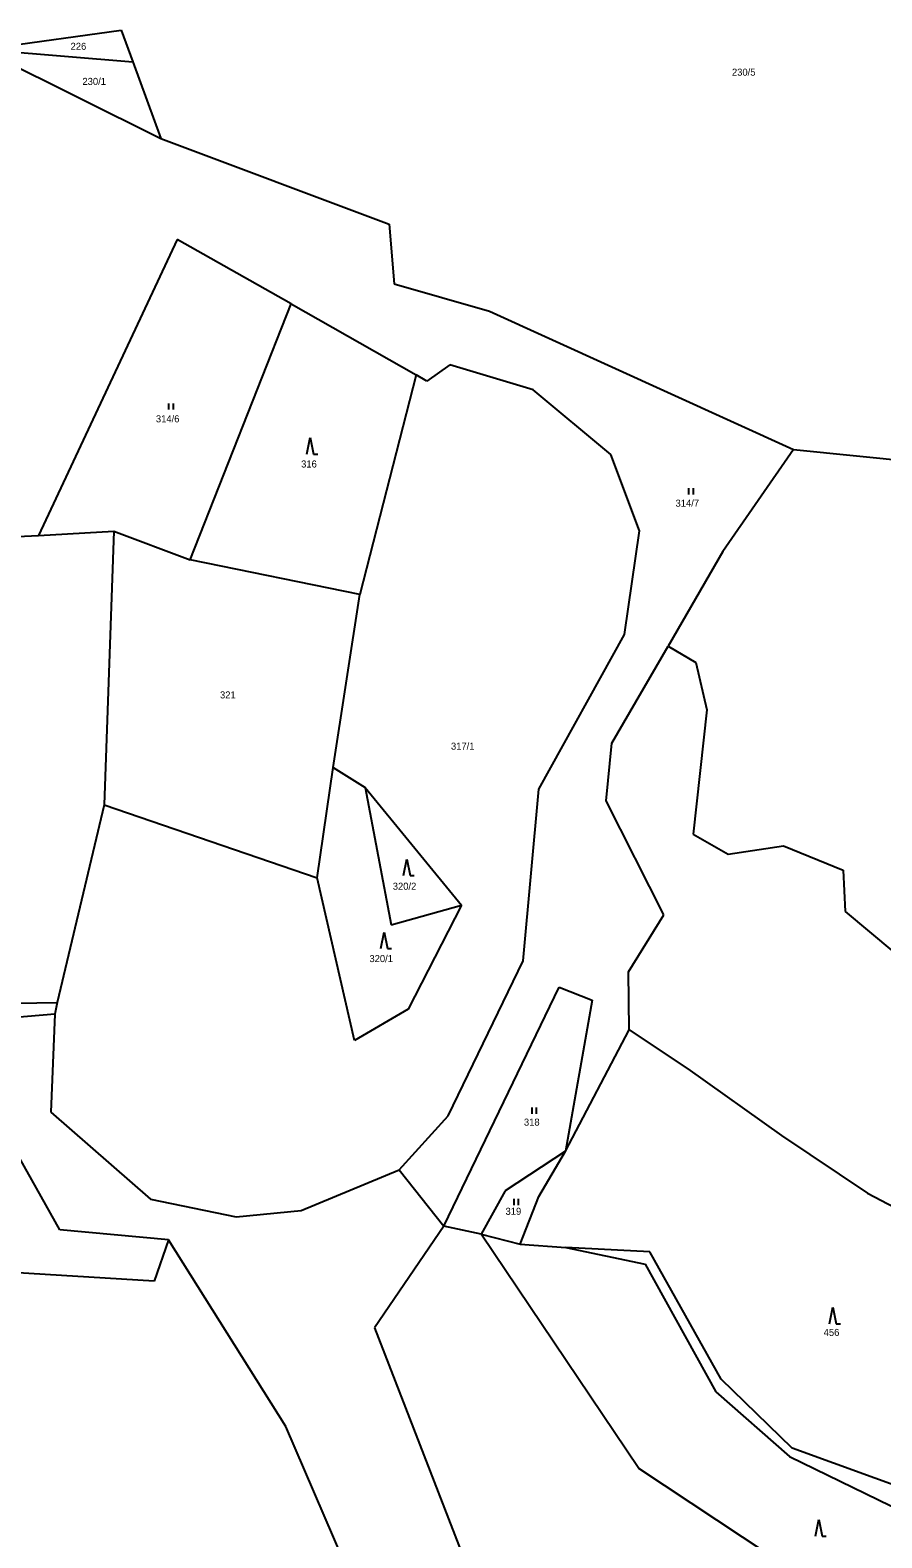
# Model space of a CAD drawing. Extents: x -794421 to -792735, y -1117671 to -1115559.
# Drawn here: x -794023.8 to -793818.1, y -1116790.7 to -1116426.7 of the extents above; entities that cross this region are included whole.
import ezdxf

# ---------------------------------------------------------------- set-up
doc = ezdxf.new("R2010")
doc.units = 0
for name, color, linetype in [('Vrstva 1', 7, 'Continuous'), ('Vrstva 14', 7, 'Continuous'), ('Vrstva 23', 7, 'Continuous')]:
    doc.layers.add(name, color=color, linetype=linetype)

msp = doc.modelspace()

# ---------------------------------------------------------------- linework, layer by layer
at = {"layer": 'Vrstva 1'}
for p, q in [((-794035.4, -1116431.36), (-794001.78, -1116426.7)), ((-794001.78, -1116426.7), (-793998.97, -1116434.36)), ((-794035.4, -1116431.36), (-793998.97, -1116434.36)), ((-794035.4, -1116431.36), (-793992.19, -1116452.85)), ((-793998.97, -1116434.36), (-793992.19, -1116452.85)), ((-793992.19, -1116452.85), (-793937.03, -1116473.51)), ((-793937.03, -1116473.51), (-793935.87, -1116487.91)), ((-793988.26, -1116477.21), (-794021.77, -1116548.68)), ((-793960.75, -1116492.81), (-793988.26, -1116477.21)), ((-793935.87, -1116487.91), (-793912.86, -1116494.55)), ((-793985.14, -1116554.57), (-793960.75, -1116492.81)), ((-793960.75, -1116492.81), (-793930.53, -1116509.89)), ((-793912.86, -1116494.55), (-793839.41, -1116527.98)), ((-793922.4, -1116507.51), (-793927.97, -1116511.44)), ((-793902.3, -1116513.51), (-793922.4, -1116507.51)), ((-793930.53, -1116509.89), (-793944.15, -1116562.94)), ((-793927.97, -1116511.44), (-793930.53, -1116509.89)), ((-793883.51, -1116529.19), (-793902.3, -1116513.51)), ((-793876.62, -1116547.54), (-793883.51, -1116529.19)), ((-793839.41, -1116527.98), (-793856.45, -1116552.56)), ((-793839.41, -1116527.98), (-793794.32, -1116532.47)), ((-794021.77, -1116548.68), (-794003.56, -1116547.66)), ((-794003.56, -1116547.66), (-794005.91, -1116613.72)), ((-794003.56, -1116547.66), (-793985.14, -1116554.57)), ((-793880.22, -1116572.61), (-793876.62, -1116547.54)), ((-794034.33, -1116549.35), (-794021.77, -1116548.68)), ((-793944.15, -1116562.94), (-793985.14, -1116554.57)), ((-793856.45, -1116552.56), (-793869.67, -1116575.46)), ((-793950.6, -1116604.75), (-793944.15, -1116562.94)), ((-793900.87, -1116609.92), (-793880.22, -1116572.61)), ((-793883.26, -1116598.83), (-793869.67, -1116575.46)), ((-793869.67, -1116575.46), (-793863.02, -1116579.4)), ((-793863.02, -1116579.4), (-793860.35, -1116590.79)), ((-793860.35, -1116590.79), (-793863.65, -1116620.81)), ((-793884.68, -1116612.78), (-793883.26, -1116598.83)), ((-793954.43, -1116631.36), (-793950.6, -1116604.75)), ((-793950.6, -1116604.75), (-793942.85, -1116609.56)), ((-793942.85, -1116609.56), (-793936.59, -1116642.74)), ((-793942.85, -1116609.56), (-793919.6, -1116637.96)), ((-793904.7, -1116651.41), (-793900.87, -1116609.92)), ((-793870.74, -1116640.26), (-793884.68, -1116612.78)), ((-794005.91, -1116613.72), (-794017.25, -1116661.45)), ((-794005.91, -1116613.72), (-793954.43, -1116631.36)), ((-793863.65, -1116620.81), (-793855.2, -1116625.61)), ((-793855.2, -1116625.61), (-793841.79, -1116623.63)), ((-793841.79, -1116623.63), (-793827.39, -1116629.52)), ((-793945.4, -1116670.61), (-793954.43, -1116631.36)), ((-793827.39, -1116629.52), (-793826.93, -1116639.52)), ((-793936.59, -1116642.74), (-793919.6, -1116637.96)), ((-793919.6, -1116637.96), (-793932.48, -1116663.06)), ((-793879.29, -1116654.03), (-793870.74, -1116640.26)), ((-793826.93, -1116639.52), (-793815.21, -1116649.33)), ((-793922.79, -1116688.79), (-793904.7, -1116651.41)), ((-793879.07, -1116668.08), (-793879.29, -1116654.03)), ((-793923.87, -1116715.45), (-793895.99, -1116657.74)), ((-793895.99, -1116657.74), (-793888.06, -1116660.88)), ((-794045.68, -1116661.89), (-794017.25, -1116661.45)), ((-794017.78, -1116664.26), (-794044.65, -1116666.54)), ((-794017.78, -1116664.26), (-794018.77, -1116687.94)), ((-794017.25, -1116661.45), (-794017.78, -1116664.26)), ((-793932.48, -1116663.06), (-793945.4, -1116670.61)), ((-793888.06, -1116660.88), (-793894.45, -1116697.37)), ((-794016.55, -1116716.31), (-794044.65, -1116666.54)), ((-793894.45, -1116697.37), (-793879.07, -1116668.08)), ((-793879.07, -1116668.08), (-793864.96, -1116677.47)), ((-793864.96, -1116677.47), (-793842.31, -1116693.57)), ((-794018.77, -1116687.94), (-793994.7, -1116708.91)), ((-793934.6, -1116701.85), (-793922.79, -1116688.79)), ((-793842.31, -1116693.57), (-793821.53, -1116707.45)), ((-793894.45, -1116697.37), (-793909.03, -1116706.89)), ((-793900.9, -1116708.33), (-793894.45, -1116697.37)), ((-793958.3, -1116711.7), (-793934.6, -1116701.85)), ((-793934.6, -1116701.85), (-793923.87, -1116715.45)), ((-793909.03, -1116706.89), (-793914.87, -1116717.35)), ((-793821.53, -1116707.45), (-793810.02, -1116713.5)), ((-793994.7, -1116708.91), (-793974.02, -1116713.23)), ((-793974.02, -1116713.23), (-793958.3, -1116711.7)), ((-793905.43, -1116719.82), (-793900.9, -1116708.33)), ((-793923.87, -1116715.45), (-793940.58, -1116740.03)), ((-793914.87, -1116717.35), (-793923.87, -1116715.45)), ((-793990.34, -1116718.72), (-794016.55, -1116716.31)), ((-793990.34, -1116718.72), (-793993.84, -1116728.72)), ((-793962.04, -1116763.8), (-793990.34, -1116718.72)), ((-793914.87, -1116717.35), (-793905.43, -1116719.82)), ((-793876.78, -1116773.96), (-793914.87, -1116717.35)), ((-793905.43, -1116719.82), (-793894.4, -1116720.61)), ((-793894.4, -1116720.61), (-793875.19, -1116724.61)), ((-793874.11, -1116721.62), (-793894.4, -1116720.61)), ((-793856.86, -1116752.39), (-793874.11, -1116721.62)), ((-793993.84, -1116728.72), (-794032.73, -1116726.38)), ((-793875.19, -1116724.61), (-793858.14, -1116755.45)), ((-793940.58, -1116740.03), (-793916.37, -1116802.53)), ((-793858.14, -1116755.45), (-793840.38, -1116771.07)), ((-793839.76, -1116769.02), (-793856.86, -1116752.39)), ((-793948.27, -1116795.8), (-793962.04, -1116763.8)), ((-793792.05, -1116786.44), (-793839.76, -1116769.02)), ((-793840.38, -1116771.07), (-793788.52, -1116796.32)), ((-793839.07, -1116798.91), (-793876.78, -1116773.96))]:
    msp.add_line(p, q, dxfattribs=at)
at = {"layer": 'Vrstva 23'}
for p, q in [((-793990.25, -1116518.32), (-793990.25, -1116516.82)), ((-793989.25, -1116516.82), (-793989.25, -1116518.32)), ((-793956.9, -1116529.07), (-793956.1, -1116525.07)), ((-793956.1, -1116525.07), (-793955.3, -1116529.07)), ((-793955.3, -1116529.07), (-793954.3, -1116529.07)), ((-793864.65, -1116538.77), (-793864.65, -1116537.27)), ((-793863.65, -1116537.27), (-793863.65, -1116538.77)), ((-793933.62, -1116630.83), (-793932.82, -1116626.83)), ((-793932.82, -1116626.83), (-793932.02, -1116630.83)), ((-793932.02, -1116630.83), (-793931.02, -1116630.83)), ((-793939.05, -1116648.44), (-793938.25, -1116644.44)), ((-793938.25, -1116644.44), (-793937.45, -1116648.44)), ((-793937.45, -1116648.44), (-793936.45, -1116648.44)), ((-793902.55, -1116688.33), (-793902.55, -1116686.83)), ((-793901.55, -1116686.83), (-793901.55, -1116688.33)), ((-793906.87, -1116710.35), (-793906.87, -1116708.85)), ((-793905.87, -1116708.85), (-793905.87, -1116710.35)), ((-793830.67, -1116739.02), (-793829.87, -1116735.02)), ((-793829.87, -1116735.02), (-793829.07, -1116739.02)), ((-793829.07, -1116739.02), (-793828.07, -1116739.02)), ((-793834.11, -1116790.27), (-793833.31, -1116786.27)), ((-793833.31, -1116786.27), (-793832.51, -1116790.27)), ((-793832.51, -1116790.27), (-793831.51, -1116790.27))]:
    msp.add_line(p, q, dxfattribs=at)

# ---------------------------------------------------------------- texts
at = {"layer": 'Vrstva 14'}
for s, p in [('226', (-794013.996, -1116431.45)), ('230/1', (-794011.132, -1116439.92)), ('230/5', (-793854.265, -1116437.69)), ('314/6', (-793993.389, -1116521.38)), ('316', (-793958.32, -1116532.29)), ('314/7', (-793867.896, -1116541.75)), ('321', (-793977.91, -1116588.04)), ('317/1', (-793922.133, -1116600.41)), ('320/2', (-793936.189, -1116634.23)), ('320/1', (-793941.822, -1116651.7)), ('318', (-793904.51, -1116691.18)), ('319', (-793908.95, -1116712.71)), ('456', (-793832.119, -1116741.95))]:
    msp.add_text(s, height=1.7, dxfattribs=at).set_placement(p)

doc.saveas('drawing.dxf')
